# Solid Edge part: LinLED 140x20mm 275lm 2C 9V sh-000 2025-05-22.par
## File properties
Author: jaroslaw.przewlocki
Template: iso metric part.par
Last saved by: jaroslaw.przewlocki
Revision: 1
Application: Solid Edge
Gęstość: 0,000 kg/m^3
Dokładność: 0,990
Username: jaroslaw.przewlocki
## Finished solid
Body 1: solid body, 669 faces, 1702 edges, 1073 vertices.
  Faces by surface: plane 362, cylinder 144, torus 66, cone 50, spline 26, sphere 21
  Edges by curve: line 1058, curve on surface 356, circle 181, ellipse 71, spline 36
Bounding box of the edges (mm; curved faces can reach further): 140.000 x 20.000 x 4.450, from (-70, -10, -1) to (70, 10, 3.45).
Cylindrical faces by radius (mm): R0.1 x6, R0.2 x46, R0.2169 x6, R0.25 x12, R0.3373 x6, R0.4 x8, R0.4006 x2, R0.4008 x2, R0.525 x2, R0.6 x20, R1 x8, R1.1 x4, R1.1989 x2, R1.199 x2, R1.2 x10, R2.15 x8
Conical faces (half-angle, radius in mm at the cone's reference point): 0.398 deg R1.1964 x2, 0.4493 deg R1.1964 x2, 0.4746 deg R1.1948 x2, 0.4758 deg R1.1948 x2, 0.5 deg R0.5056 x4, 0.5 deg R1.0082 x4, 1 deg R0.5511 x2, 10 deg R0.2132 x4, 10 deg R0.4132 x4, 16.0099 deg R1.1053 x2, 16.1249 deg R1.1279 x2, 18.8604 deg R1.0669 x4, 19.5041 deg R0.5138 x2, 19.8244 deg R0.5099 x2, 27.363 deg R0.6214 x2, 40.6434 deg R0.5161 x2, 43.3309 deg R0.4892 x2, 45 deg R0.575 x2, 45 deg R0.625 x4
Toroidal faces (ring radius, tube radius in mm): R0.0958 r0.3997 x4, R0.1076 r0.4 x2, R0.1101 r0.4001 x2, R0.1217 r0.4 x2, R0.1234 r0.4 x2, R0.1626 r0.228 x2, R0.1634 r0.2287 x2, R0.3287 r0.2001 x2, R0.3684 r0.2151 x2, R0.3703 r0.4 x2, R0.3818 r0.2 x4, R0.4166 r0.3983 x2, R0.5981 r0.197 x2, R0.5982 r0.197 x2, R0.6009 r0.3968 x2, R0.6009 r0.3969 x2, R0.6227 r0.2 x2, R0.6235 r0.2 x2, R0.8 r0.2 x4, R0.8522 r0.3 x2, R0.9002 r0.2 x2, R0.9018 r0.2 x2, R0.9197 r0.223 x2, R0.9365 r0.2 x2, R0.9663 r0.2263 x2, R0.9665 r0.2263 x2, R1.2 r0.1 x2, R1.429 r1.2 x2, R1.8741 r0.2175 x2, R1.9007 r0.2 x2
Spherical faces by radius (mm): R0.1 x5, R0.2 x12, R0.6 x4
Planar faces by outward normal: +x 42, +y 39, +z 54, -x 42, -y 39, -z 9, oblique 137
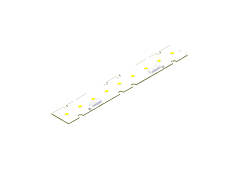
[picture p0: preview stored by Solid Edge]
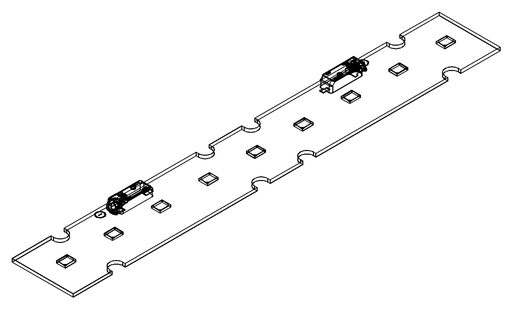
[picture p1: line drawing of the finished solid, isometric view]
